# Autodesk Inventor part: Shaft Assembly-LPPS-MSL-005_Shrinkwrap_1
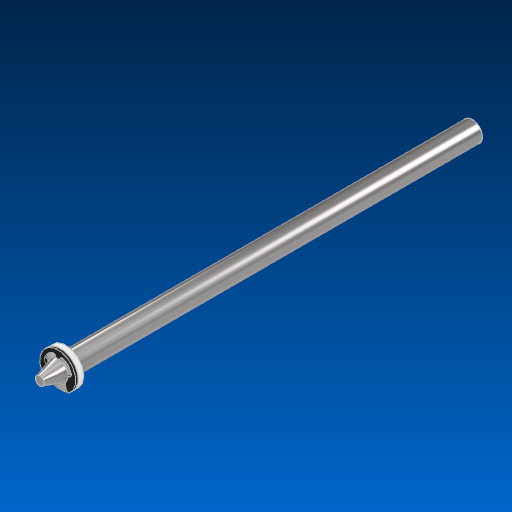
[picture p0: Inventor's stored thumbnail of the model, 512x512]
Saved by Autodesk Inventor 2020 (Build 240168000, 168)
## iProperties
Created: 2019-08
Part Number: Shaft Assembly-LPPS-MSL-005_Shrinkwrap_1
Material: Generic
Document SubType Name: Modeling
Designer: J. Nielson
Density: 1 g/cm^3
Appearance: Default
Author: J. Nielson
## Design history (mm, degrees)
node "Assembly1" dims "d0" = 10
body "Solid1"
node "Part1:1" dims "d0" = 10
node "Part2:1" dims "d0" = 10
body "Solid2"
node "Part3:1" dims "d0" = 10
body "Solid3"
